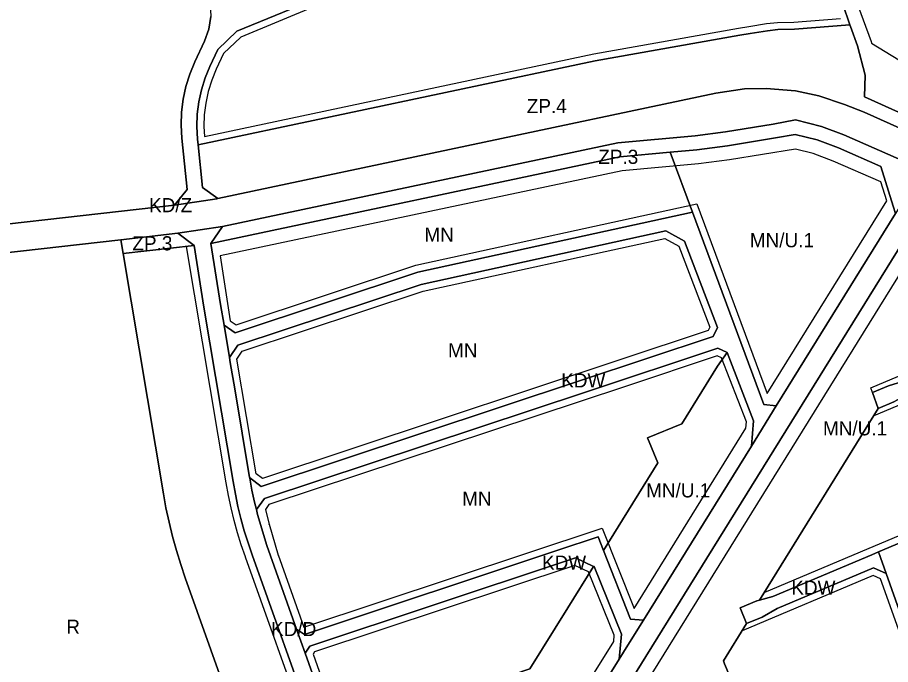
# Model space of a CAD drawing. Extents: x 7438199 to 7440548, y 5549253 to 5551017.
# Drawn here: x 7439598 to 7440215, y 5549804 to 5550261 of the extents above; entities that cross this region are included whole.
import ezdxf

# ---------------------------------------------------------------- set-up
doc = ezdxf.new("R2010")
doc.units = 0
for name, color, linetype in [('linie_rozgraniczajace', 7, 'Continuous'), ('linie_zabudowy_nieprzekraczalne', 7, 'Continuous'), ('oznaczenia_przeznaczen', 7, 'Continuous')]:
    doc.layers.add(name, color=color, linetype=linetype)

msp = doc.modelspace()

# ---------------------------------------------------------------- linework, layer by layer
at = {"layer": 'linie_rozgraniczajace'}
for points in [[(7439595.04, 5550676.91), (7439607.46, 5550678.53), (7439619.96, 5550679.38), (7439662.33, 5550680.91), (7439673.37, 5550671.32), (7439677.54, 5550631.88), (7439678.34, 5550625.07), (7439680.39, 5550611.52), (7439711.53, 5550433.54), (7439713.24, 5550422.53), (7439733.89, 5550271.3), (7439734.25, 5550262.24), (7439732.89, 5550253.29), (7439729.85, 5550244.75), (7439722.96, 5550230.02), (7439719.43, 5550221.49), (7439716.69, 5550212.68), (7439714.74, 5550203.66), (7439713.62, 5550194.5), (7439713.32, 5550185.27), (7439713.86, 5550176.05), (7439717.6, 5550139.86), (7439708.69, 5550128.79), (7439512.65, 5550106.55)], [(7440176.26, 5550285.71), (7440186.13, 5550256.24), (7440146.82, 5550253.26), (7440135.16, 5550252.88), (7440127.83, 5550252.14), (7440115.53, 5550250.21), (7440108.24, 5550249.01), (7440006.11, 5550230.82), (7439725.4, 5550171.35), (7439724.97, 5550175.53), (7439724.46, 5550184.3), (7439724.74, 5550193.07), (7439725.81, 5550201.79), (7439727.66, 5550210.37), (7439730.27, 5550218.76), (7439733.63, 5550226.87), (7439739.27, 5550238.92), (7439752.74, 5550251.81), (7439806.86, 5550274.25)], [(7439806.86, 5550274.25), (7439752.74, 5550251.81), (7439739.27, 5550238.92), (7439733.63, 5550226.87), (7439730.27, 5550218.76), (7439727.66, 5550210.37), (7439725.81, 5550201.79), (7439724.74, 5550193.07), (7439724.46, 5550184.3), (7439724.97, 5550175.53), (7439725.4, 5550171.35), (7439728.52, 5550141.21), (7439739.32, 5550133.41), (7439738.46, 5550133.23), (7439708.69, 5550128.79), (7439717.6, 5550139.86), (7439713.86, 5550176.05), (7439713.32, 5550185.27), (7439713.62, 5550194.5), (7439714.74, 5550203.66), (7439716.69, 5550212.68), (7439719.43, 5550221.49), (7439722.96, 5550230.02), (7439729.85, 5550244.75), (7439732.89, 5550253.29), (7439734.25, 5550262.24)], [(7439512.65, 5550106.55), (7439708.69, 5550128.79), (7439738.46, 5550133.23), (7439739.32, 5550133.41), (7440091.38, 5550208), (7440111.64, 5550210.92), (7440127.01, 5550211.36), (7440147.62, 5550209.57), (7440164.13, 5550206.11), (7440182.3, 5550200.05), (7440196.18, 5550194.5), (7440239.79, 5550174.9), (7440268.06, 5550162.2)], [(7440228.49, 5550158.06), (7440181.83, 5550178.47), (7440166.02, 5550184.48), (7440147.76, 5550189.01), (7440131.92, 5550186.14), (7440098.13, 5550180.68), (7440076.8, 5550177.8), (7440022.09, 5550172.88), (7439742.6, 5550113.67), (7439710.99, 5550108.93), (7439670.68, 5550104.35), (7439514.05, 5550086.59)], [(7440227.08, 5550005.17), (7440213.47, 5550001.07), (7440202.09, 5549996.27), (7440206.12, 5549984.95), (7440122.18, 5549849.49), (7440120.23, 5549848.95), (7440108.63, 5549844.06), (7440113.1, 5549832.93), (7440096.64, 5549806.47), (7440097.49, 5549804.44), (7440104.04, 5549788.87), (7440090.03, 5549782.03), (7440089.49, 5549781.67), (7440080.98, 5549777.82), (7440073.14, 5549774.28), (7440059.1, 5549767.45), (7440065.46, 5549752.89), (7440031.9, 5549698.99), (7440013.26, 5549748.91), (7440014.17, 5549765.09), (7440041.95, 5549809.72), (7440239.68, 5550128.82)], [(7440239.68, 5550128.82), (7440041.95, 5549809.72), (7440014.17, 5549765.09)], [(7439892.09, 5549597.4), (7440023.05, 5549807.75), (7440029.2, 5549817.63), (7440040.13, 5549835.27), (7440116.48, 5549958.48), (7440134.07, 5549986.87), (7440218.28, 5550122.77)], [(7439807.99, 5549756.65), (7439763.48, 5549881.63), (7439760.61, 5549890.06), (7439758, 5549898.57), (7439755.63, 5549907.15), (7439753.52, 5549915.81), (7439751.66, 5549924.51), (7439750.06, 5549933.27), (7439729.38, 5550056.61), (7439722.49, 5550100.18), (7439710.99, 5550108.93), (7439742.6, 5550113.67), (7439734.4, 5550101.63), (7439741.22, 5550058.54), (7439743.68, 5550043.88), (7439747.5, 5550021.1), (7439748.09, 5550017.59), (7439751.23, 5549998.84), (7439761.75, 5549936.1), (7439761.81, 5549935.78), (7439763.37, 5549927.19), (7439765.2, 5549918.66), (7439766.53, 5549913.53), (7439767.42, 5549910.07), (7439773.86, 5549888.23), (7439794.94, 5549829.04), (7439801.04, 5549811.94), (7439819.27, 5549760.76)], [(7439514.05, 5550086.59), (7439670.68, 5550104.35), (7439672.33, 5550094.48), (7439700.81, 5549924.64), (7439702.61, 5549914.8), (7439704.78, 5549904.66), (7439707.24, 5549894.58), (7439709.99, 5549884.58), (7439713.04, 5549874.67), (7439716.26, 5549865.2), (7439761.02, 5549739.54)], [(7439761.02, 5549739.54), (7439716.26, 5549865.2), (7439713.04, 5549874.67), (7439709.99, 5549884.58), (7439707.24, 5549894.58), (7439704.78, 5549904.66), (7439702.61, 5549914.8), (7439700.81, 5549924.64), (7439672.33, 5550094.48), (7439722.49, 5550100.18), (7439729.38, 5550056.61), (7439750.06, 5549933.27), (7439751.66, 5549924.51), (7439753.52, 5549915.81), (7439755.63, 5549907.15), (7439758, 5549898.57), (7439760.61, 5549890.06), (7439763.48, 5549881.63), (7439807.99, 5549756.65)], [(7440242.24, 5549782.61), (7440211.65, 5549868.35), (7440206.23, 5549883.55), (7440415.19, 5549971.57)]]:
    msp.add_lwpolyline(points, dxfattribs=at)
for points in [[(7440176.26, 5550285.71), (7440184.28, 5550297.74), (7440234.78, 5550262.81), (7440284.54, 5550229.12), (7440268.76, 5550202.14), (7440261.99, 5550191.28), (7440254.35, 5550179.32), (7440196.44, 5550205.34), (7440196.82, 5550220.59), (7440191.47, 5550241.49), (7440186.53, 5550255.03), (7440186.13, 5550256.24)], [(7439725.4, 5550171.35), (7440006.11, 5550230.82), (7440108.24, 5550249.01), (7440115.53, 5550250.21), (7440127.83, 5550252.14), (7440135.16, 5550252.88), (7440146.82, 5550253.26), (7440186.13, 5550256.24), (7440186.53, 5550255.03), (7440191.47, 5550241.49), (7440196.82, 5550220.59), (7440196.44, 5550205.34), (7440254.35, 5550179.32), (7440254.29, 5550179.23), (7440239.79, 5550174.9), (7440196.18, 5550194.5), (7440182.3, 5550200.05), (7440164.13, 5550206.11), (7440147.62, 5550209.57), (7440127.01, 5550211.36), (7440111.64, 5550210.92), (7440091.38, 5550208), (7439739.32, 5550133.41), (7439728.52, 5550141.21)], [(7439734.4, 5550101.63), (7439742.6, 5550113.67), (7440022.09, 5550172.88), (7440076.8, 5550177.8), (7440098.13, 5550180.68), (7440131.92, 5550186.14), (7440147.76, 5550189.01), (7440166.02, 5550184.48), (7440181.83, 5550178.47), (7440228.49, 5550158.06), (7440232.34, 5550145.46), (7440218.28, 5550122.77), (7440216.66, 5550128.03), (7440208.01, 5550156.1), (7440178.05, 5550169.21), (7440163.03, 5550174.92), (7440147.44, 5550178.79), (7440133.61, 5550176.28), (7440099.6, 5550170.79), (7440077.91, 5550167.86), (7440059.07, 5550166.16), (7440023.58, 5550162.97)], [(7440059.07, 5550166.16), (7440077.91, 5550167.86), (7440099.6, 5550170.79), (7440133.61, 5550176.28), (7440147.44, 5550178.79), (7440163.03, 5550174.92), (7440178.05, 5550169.21), (7440208.01, 5550156.1), (7440216.66, 5550128.03), (7440218.28, 5550122.77), (7440134.07, 5549986.87), (7440125.24, 5549987.71), (7440074.8, 5550123.91)], [(7439734.4, 5550101.63), (7440023.58, 5550162.97), (7440059.07, 5550166.16), (7440074.8, 5550123.91), (7439880.68, 5550081.44), (7439751.46, 5550038.56), (7439743.68, 5550043.88), (7439741.22, 5550058.54)], [(7439743.68, 5550043.88), (7439751.46, 5550038.56), (7439880.68, 5550081.44), (7440074.8, 5550123.91), (7440125.24, 5549987.71), (7440134.07, 5549986.87), (7440116.48, 5549958.48), (7440118.04, 5549976.26), (7440099.22, 5550024.48), (7440092.7, 5550027.58), (7439999.13, 5549996.53), (7439772.34, 5549921.27), (7439766.53, 5549913.53), (7439765.2, 5549918.66), (7439763.37, 5549927.19), (7439761.81, 5549935.78), (7439761.75, 5549936.1), (7439769.94, 5549929.95), (7439995.73, 5550004.88), (7440089.49, 5550036), (7440092.46, 5550042.24), (7440069.23, 5550103.35), (7440055.92, 5550110.57), (7439883.07, 5550072.75), (7439753.31, 5550029.69), (7439747.5, 5550021.1)], [(7439670.68, 5550104.35), (7439710.99, 5550108.93), (7439722.49, 5550100.18), (7439672.33, 5550094.48)], [(7439747.5, 5550021.1), (7439753.31, 5550029.69), (7439883.07, 5550072.75), (7440055.92, 5550110.57), (7440069.23, 5550103.35), (7440092.46, 5550042.24), (7440089.49, 5550036), (7439995.73, 5550004.88), (7439769.94, 5549929.95), (7439761.75, 5549936.1), (7439751.23, 5549998.84), (7439748.09, 5550017.59)], [(7440202.09, 5549996.27), (7440213.47, 5550001.07), (7440227.08, 5550005.17), (7440373.11, 5550066.69), (7440375.68, 5550073.21), (7440383.8, 5550055.48), (7440376.51, 5550058.35), (7440230.18, 5549996.72), (7440217.22, 5549989.63), (7440206.12, 5549984.95)], [(7440122.18, 5549849.49), (7440206.12, 5549984.95), (7440217.22, 5549989.63), (7440230.18, 5549996.72), (7440376.51, 5550058.35), (7440383.8, 5550055.48), (7440412.59, 5549992.59), (7440418.47, 5549979.89), (7440415.19, 5549971.57), (7440206.23, 5549883.55), (7440201.62, 5549881.61), (7440131.53, 5549852.08)], [(7439766.53, 5549913.53), (7439772.34, 5549921.27), (7439999.13, 5549996.53), (7440092.7, 5550027.58), (7440099.22, 5550024.48), (7440092.61, 5550014.88), (7440067.34, 5549974.09), (7440043.12, 5549964.26), (7440050.29, 5549946.58), (7440011.91, 5549884.64), (7440008.15, 5549894.17), (7439979.69, 5549884.72), (7439800.48, 5549825.25), (7439794.94, 5549829.04), (7439773.86, 5549888.23), (7439767.42, 5549910.07)], [(7440011.91, 5549884.64), (7440050.29, 5549946.58), (7440043.12, 5549964.26), (7440067.34, 5549974.09), (7440092.61, 5550014.88), (7440099.22, 5550024.48), (7440118.04, 5549976.26), (7440116.48, 5549958.48), (7440040.13, 5549835.27), (7440031.12, 5549836.04)], [(7439794.94, 5549829.04), (7439800.48, 5549825.25), (7439979.69, 5549884.72), (7440008.15, 5549894.17), (7440011.91, 5549884.64), (7440031.12, 5549836.04), (7440040.13, 5549835.27), (7440029.2, 5549817.63), (7440023.05, 5549807.75), (7440024.59, 5549825.51), (7440005.3, 5549873.22), (7440004.94, 5549873.39), (7439992.06, 5549879.34), (7439982.14, 5549876.05), (7439804.32, 5549817.04), (7439801.04, 5549811.94)], [(7440108.63, 5549844.06), (7440120.23, 5549848.95), (7440122.18, 5549849.49), (7440131.53, 5549852.08), (7440201.62, 5549881.61), (7440206.23, 5549883.55), (7440211.65, 5549868.35), (7440202.69, 5549872.29), (7440134.78, 5549843.69), (7440123.98, 5549837.51), (7440113.1, 5549832.93)], [(7439801.04, 5549811.94), (7439804.32, 5549817.04), (7439982.14, 5549876.05), (7439992.06, 5549879.34), (7440004.94, 5549873.39), (7439986.73, 5549844.01), (7439959.89, 5549800.9), (7439936.93, 5549793.24), (7439943.28, 5549774.21), (7439862.34, 5549644.19), (7439849.66, 5549679.19), (7439819.27, 5549760.76)], [(7439862.34, 5549644.19), (7439943.28, 5549774.21), (7439936.93, 5549793.24), (7439959.89, 5549800.9), (7439986.73, 5549844.01), (7440004.94, 5549873.39), (7440005.3, 5549873.22), (7440024.59, 5549825.51), (7440023.05, 5549807.75), (7439892.09, 5549597.4), (7439881.11, 5549597.9), (7439876.67, 5549604.63)], [(7440031.9, 5549698.99), (7440065.46, 5549752.89), (7440059.1, 5549767.45), (7440073.14, 5549774.28), (7440080.98, 5549777.82), (7440089.49, 5549781.67), (7440090.03, 5549782.03), (7440104.04, 5549788.87), (7440097.49, 5549804.44), (7440096.64, 5549806.47), (7440113.1, 5549832.93), (7440123.98, 5549837.51), (7440134.78, 5549843.69), (7440202.69, 5549872.29), (7440211.65, 5549868.35), (7440242.24, 5549782.61), (7440238.14, 5549773.3), (7440041.78, 5549690.58), (7440033.47, 5549694.77)]]:
    msp.add_lwpolyline(points, close=True, dxfattribs=at)
at = {"layer": 'linie_zabudowy_nieprzekraczalne'}
for points in [[(7440182.55, 5550295.15), (7440201.03, 5550244.45), (7440201.32, 5550243.34), (7440263.66, 5550205.25), (7440280.33, 5550231.97), (7440299.34, 5550262.45)], [(7439808.69, 5550269.6), (7439755.52, 5550247.55), (7439743.4, 5550235.95), (7439738.21, 5550224.85), (7439734.98, 5550217.05), (7439732.5, 5550209.1), (7439730.75, 5550200.96), (7439729.73, 5550192.69), (7439729.46, 5550184.36), (7439729.87, 5550177.4), (7440005.15, 5550235.73), (7440107.4, 5550253.94), (7440114.74, 5550255.15), (7440127.19, 5550257.1), (7440134.83, 5550257.87), (7440146.55, 5550258.25), (7440179.35, 5550260.74)], [(7439752.24, 5550044.08), (7439879.36, 5550086.27), (7440077.98, 5550129.72), (7440127.67, 5549995.53), (7440212.11, 5550131.8), (7440207.89, 5550145.24), (7440174.26, 5550159.95), (7440160.04, 5550165.36), (7440147.68, 5550168.42), (7440101.07, 5550160.9), (7440079.03, 5550157.92), (7440025.07, 5550153.06), (7439740.85, 5550092.85), (7439748.12, 5550046.89), (7439752.24, 5550044.08)], [(7440202.09, 5549996.27), (7440200.97, 5549999.6), (7440369.23, 5550070.48), (7440370.25, 5550073.06), (7440349.66, 5550118.04), (7440346.94, 5550119.43), (7440242.77, 5550114.82), (7440050.44, 5549804.44), (7440017.57, 5549751.65), (7440037.47, 5549698.35), (7440041.97, 5549696.09), (7440234.37, 5549777.13), (7440236.86, 5549782.8), (7440207.67, 5549864.64), (7440202.65, 5549866.85), (7440109.9, 5549827.78)], [(7440085.89, 5550040.07), (7439770.85, 5549935.52), (7439766.35, 5549938.9), (7439752.76, 5550019.95), (7439756.5, 5550025.48), (7439884.39, 5550067.92), (7440055.17, 5550105.28), (7440065.22, 5550099.84), (7440087.03, 5550042.46), (7440085.89, 5550040.07)], [(7439805.85, 5549477.79), (7439868.24, 5549577.99), (7439833.69, 5549673.35), (7439833.71, 5549673.31), (7439803.31, 5549754.91), (7439803.28, 5549754.98), (7439758.77, 5549879.95), (7439758.74, 5549880.02), (7439755.85, 5549888.52), (7439753.19, 5549897.17), (7439750.79, 5549905.9), (7439748.64, 5549914.69), (7439746.76, 5549923.54), (7439745.14, 5549932.37), (7439745.13, 5549932.45), (7439717.11, 5550099.56)], [(7440125.6, 5549855.01), (7440204.29, 5549888.16), (7440411.31, 5549975.36), (7440413.03, 5549979.73), (7440408.05, 5549990.5), (7440380.09, 5550051.57), (7440376.57, 5550052.95), (7440202.94, 5549979.81)], [(7439800.18, 5549830.42), (7440011.06, 5549900.4), (7440033.52, 5549843.57), (7440112.57, 5549971.15), (7440112.95, 5549975.54), (7440095.29, 5550020.81), (7440092.37, 5550022.2), (7440027.43, 5550000.65), (7439775.4, 5549917.01), (7439772.88, 5549913.67), (7439775.66, 5549902.98), (7439775.62, 5549903.13), (7439782.05, 5549881.29), (7439781.97, 5549881.56), (7439800.18, 5549830.42)], [(7439991.75, 5549873.98), (7439807.57, 5549812.86), (7439806.57, 5549811.3), (7439823.98, 5549762.44), (7439823.95, 5549762.51), (7439854.34, 5549680.94), (7439854.36, 5549680.9), (7439881.16, 5549606.89), (7439883.77, 5549602.95), (7440019.13, 5549820.36), (7440019.51, 5549824.75), (7440001.4, 5549869.52), (7439991.75, 5549873.98)]]:
    msp.add_lwpolyline(points, dxfattribs=at)

# ---------------------------------------------------------------- texts
at = {"layer": 'oznaczenia_przeznaczen'}
for s, p in [('ZP.4', (7439957.7, 5550193.84)), ('ZP.3', (7440008.23, 5550157.97)), ('KD/Z', (7439690.66, 5550123.79)), ('MN', (7439885.3, 5550102.93)), ('MN/U.1', (7440115.36, 5550098.97)), ('ZP.3', (7439678.89, 5550096.81)), ('MN', (7439902.02, 5550021.17)), ('KDW', (7439982.03, 5549999.88)), ('MN/U.1', (7440167.07, 5549965.98)), ('MN/U.1', (7440042.06, 5549922.12)), ('MN', (7439912, 5549916.28)), ('KDW', (7439968.44, 5549871.05)), ('KDW', (7440144.69, 5549853.34)), ('R', (7439632.16, 5549825.69)), ('KD/D', (7439776.91, 5549824.04))]:
    msp.add_text(s, height=10, dxfattribs=at).set_placement(p)

doc.saveas('drawing.dxf')
